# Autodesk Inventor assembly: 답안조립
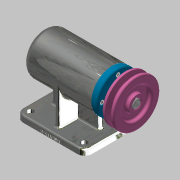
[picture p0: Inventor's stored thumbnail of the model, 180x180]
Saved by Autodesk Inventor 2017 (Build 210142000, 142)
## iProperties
Part Number: 답안조립
Material: 일반
Document SubType Name: Assembly
Designer: mrc
Author: mrc
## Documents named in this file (12)
- C:\Users\mrc\Desktop\701004V1033\답안조립.iam
- C:\Users\mrc\Desktop\701004V1033\본체.ipt
- C:\Users\mrc\Desktop\701004V1033\V벨트풀리.ipt
- C:\Users\mrc\Desktop\701004V1033\멈춤나사 M3.ipt
- C:\Users\mrc\Desktop\701004V1033\베어링 6004.ipt
- C:\Users\mrc\Desktop\701004V1033\베어링 51202.ipt
- C:\Users\mrc\Desktop\701004V1033\볼트 M4.ipt
- C:\Users\mrc\Desktop\701004V1033\어댑터슬리브.ipt
- C:\Users\mrc\Desktop\701004V1033\오일 실.ipt
- C:\Users\mrc\Desktop\701004V1033\축.ipt
- C:\Users\mrc\Desktop\701004V1033\커버.ipt
- C:\Users\mrc\Desktop\701004V1033\키 5 x 5 x 16.ipt
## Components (1 placed, 1 different names)
1. V벨트풀리:1 — 플러쉬:1, 각도:1
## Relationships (2: Flush 1, Angle 1)
- 플러쉬:1 [Flush]: V벨트풀리:1
- 각도:1 [Angle]: V벨트풀리:1
